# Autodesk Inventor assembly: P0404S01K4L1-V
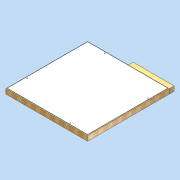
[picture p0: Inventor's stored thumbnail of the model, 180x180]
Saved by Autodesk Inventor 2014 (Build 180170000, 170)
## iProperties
Created: 2011-04
Part Number: P0404S01K4L1-V
Document SubType Name: Assembly
Designer: david.appleford
Description: 1w x 1w 01 Panel - 4 Locks 1 Lug
Mass: 22000 g
Surface Area: 31888.2 cm^2
Volume: 108275 cm^3
Density: 0.203187 g/cm^3
Cost Center: £89.00
Justset: False
Title: 1w x 1w 01 Panel - 4 Locks 1 Lug
Author: david.appleford
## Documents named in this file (3)
- C:\Documents and Settings\john.everitt\Local Settings\My Documents\Vault\Production MkII\VIRTUAL ELEMENTS\Virtual Walls\Virtual Timber + MgO\P0404S01K4L1-V.iam
- C:\Documents and Settings\john.everitt\Local Settings\My Documents\Vault\Production MkII\VIRTUAL ELEMENTS\Virtual Lugs\Superceded Lugs\LA02C3V.ipt
- C:\Documents and Settings\john.everitt\Local Settings\My Documents\Vault\Production MkII\Virtual Elements\Virtual Walls\Virtual Timber + MgO\P0404S01K4-V.ipt
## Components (2 placed, 2 different names)
1. P0404S01K4-V:1 — Mate:4, Flush:7, Flush:8
2. LA02C3V:3 — Mate:4, Flush:7, Flush:8
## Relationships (3: Flush 2, Mate 1)
- Mate:4: P0404S01K4-V:1 ↔ LA02C3V:3
- Flush:7: P0404S01K4-V:1 ↔ LA02C3V:3
- Flush:8: P0404S01K4-V:1 ↔ LA02C3V:3
## Named parameters: t = 1 mm, Cl = 2 mm
